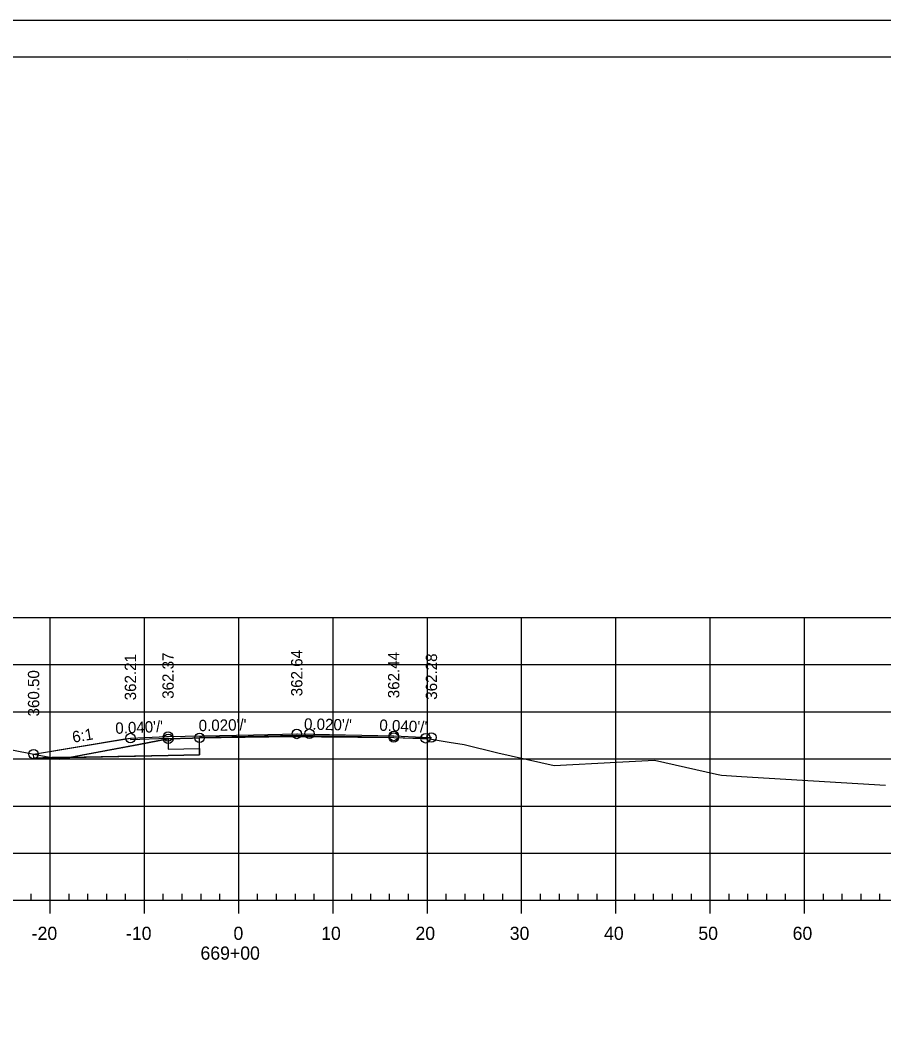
# Model space of a CAD drawing. Extents: x 1359801 to 1362404, y 372415 to 374228.
# Drawn here: x 1359948.2 to 1360039.8, y 373694.6 to 373801.3 of the extents above; entities that cross this region are included whole.
import ezdxf

# ---------------------------------------------------------------- set-up
doc = ezdxf.new("R2010")
doc.units = 0
for name, color, linetype in [('S_DRG_PT_SYM', 7, 'Continuous'), ('S_ELECTRIC_UTILITIES_ANNOT', 7, 'Continuous'), ('S_IRON_PIN', 7, 'Continuous'), ('S_MAILBOX', 7, 'Continuous'), ('S_PRIMARY_CTL', 7, 'Continuous'), ('S_SANITARY_SEWER', 7, 'Continuous'), ('S_SHOULDER', 7, 'Continuous'), ('S_UNDERGROUND_CABLE', 7, 'Continuous'), ('S_UTL_PT_SYM', 7, 'Continuous'), ('S_WATER_UTILITIES', 7, 'Continuous')]:
    doc.layers.add(name, color=color, linetype=linetype)

msp = doc.modelspace()

# ---------------------------------------------------------------- linework, layer by layer
at = {"layer": 'S_DRG_PT_SYM'}
msp.add_lwpolyline([(1359936.81, 373725.9), (1359952.38, 373722.9), (1359960.74, 373724.47), (1359963.88, 373725.06), (1359966.43, 373725.14), (1359967.2, 373725.16), (1359969.5, 373725.19), (1359977.07, 373725.3), (1359980.14, 373725.27), (1359987.78, 373725.21), (1359990.13, 373725.15), (1359991.16, 373725.12), (1359993.65, 373724.7), (1359995.24, 373724.46), (1359998.82, 373723.57), (1360004.81, 373722.25), (1360011.41, 373722.59), (1360015.44, 373722.79), (1360022.02, 373721.32), (1360022.56, 373721.21), (1360024.66, 373721.07), (1360039.94, 373720.16)], dxfattribs=at)
at = {"layer": 'S_ELECTRIC_UTILITIES_ANNOT'}
for p, q in [((1359987.78, 373725.21), (1359977.5, 373725.41)), ((1359953.44, 373723.1), (1359951.54, 373723.07)), ((1359951.54, 373723.07), (1359951.54, 373723.07)), ((1359953.44, 373723.1), (1359963.85, 373723.31))]:
    msp.add_line(p, q, dxfattribs=at)
for points in [[(1359967.2, 373725.16), (1359966.43, 373725.14), (1359963.88, 373725.06), (1359960.74, 373724.47), (1359953.44, 373723.1)], [(1359963.85, 373723.31), (1359967.2, 373723.38), (1359967.2, 373725.16)], [(1359977.5, 373725.41), (1359967.2, 373725.21), (1359967.2, 373725.16)], [(1359967.2, 373725.16), (1359969.5, 373725.19), (1359977.07, 373725.3), (1359980.14, 373725.27), (1359987.78, 373725.21)], [(1359951.54, 373723.07), (1359952.38, 373722.9), (1359953.44, 373723.1)]]:
    msp.add_lwpolyline(points, dxfattribs=at)
msp.add_lwpolyline([(1359949.6, 373723.03), (1359949.59, 373723.44), (1359951.54, 373723.07)], close=True, dxfattribs=at)
at = {"layer": 'S_MAILBOX'}
for p, q in [((1359826.35, 373737.94), (1360116.35, 373737.94)), ((1359951.35, 373707.94), (1359951.35, 373737.94)), ((1359961.35, 373707.94), (1359961.35, 373737.94)), ((1359971.35, 373707.94), (1359971.35, 373737.94)), ((1359981.35, 373707.94), (1359981.35, 373737.94)), ((1359991.35, 373707.94), (1359991.35, 373737.94)), ((1360001.35, 373707.94), (1360001.35, 373737.94)), ((1360011.35, 373707.94), (1360011.35, 373737.94)), ((1360021.35, 373707.94), (1360021.35, 373737.94)), ((1360031.35, 373707.94), (1360031.35, 373737.94)), ((1359826.35, 373732.94), (1360116.35, 373732.94)), ((1359826.35, 373727.94), (1360116.35, 373727.94)), ((1359826.35, 373722.94), (1360116.35, 373722.94)), ((1359826.35, 373717.94), (1360116.35, 373717.94)), ((1359826.35, 373712.94), (1360116.35, 373712.94)), ((1359826.35, 373707.94), (1360116.35, 373707.94))]:
    msp.add_line(p, q, dxfattribs=at)
at = {"layer": 'S_SANITARY_SEWER'}
msp.add_lwpolyline([(1359949.59, 373723.44), (1359959.25, 373725.05), (1359959.86, 373725.15), (1359963.7, 373725.3), (1359963.85, 373725.31), (1359972.91, 373725.49), (1359977.5, 373725.58), (1359977.57, 373725.58), (1359977.57, 373725.58), (1359977.57, 373725.58), (1359987.78, 373725.37), (1359990.88, 373725.25), (1359991.78, 373725.21)], dxfattribs=at)
at = {"layer": 'S_SHOULDER'}
msp.add_line((1359800.95, 373801.29), (1360134.28, 373801.29), dxfattribs=at)
for points in [[(1359800.94, 373801.29), (1360134.28, 373801.29), (1360134.28, 373587.95), (1359800.94, 373587.95)], [(1360047.27, 373797.4), (1360047.27, 373787.52), (1360083, 373787.52), (1360083, 373784.6), (1360106.2, 373784.6), (1360106.2, 373760.26), (1360129.53, 373760.26), (1360129.53, 373591.94), (1359813.35, 373591.94), (1359813.35, 373797.4)]]:
    msp.add_lwpolyline(points, close=True, dxfattribs=at)
for points in [[(1359949.59, 373723.44), (1359959.86, 373725.15), (1359959.87, 373724.98), (1359963.86, 373725.14)], [(1359963.86, 373725.14), (1359963.88, 373723.98), (1359967.2, 373724.04)], [(1359967.2, 373724.04), (1359967.2, 373723.38), (1359963.85, 373723.31), (1359949.6, 373723.03), (1359949.59, 373723.44)]]:
    msp.add_lwpolyline(points, dxfattribs=at)
for centre in [(1359977.5, 373725.58), (1359978.85, 373725.61), (1359959.86, 373725.15), (1359963.85, 373725.31), (1359963.88, 373725.06), (1359967.2, 373725.16), (1359987.78, 373725.37), (1359987.78, 373725.21), (1359991.16, 373725.12), (1359991.78, 373725.21), (1359949.59, 373723.44)]:
    msp.add_circle(centre, 0.5, dxfattribs=at)
at = {"layer": 'S_UNDERGROUND_CABLE'}
msp.add_lwpolyline([(1359949.6, 373723.03), (1359963.85, 373723.31), (1359967.2, 373723.38), (1359967.2, 373725.21), (1359977.5, 373725.41), (1359987.78, 373725.21), (1359991.78, 373725.05)], dxfattribs=at)
at = {"layer": 'S_UTL_PT_SYM'}
for p, q in [((1359813.35, 373797.4), (1360129.53, 373797.4)), ((1359965.87, 373797.14), (1359965.87, 373797.14)), ((1359965.87, 373797.14), (1359965.87, 373797.14))]:
    msp.add_line(p, q, dxfattribs=at)
at = {"layer": 'S_WATER_UTILITIES'}
for p, q in [((1359826.35, 373707.94), (1360116.35, 373707.94)), ((1359949.35, 373707.94), (1359949.35, 373708.64)), ((1359951.35, 373706.54), (1359951.35, 373707.94)), ((1359953.35, 373707.94), (1359953.35, 373708.64)), ((1359955.35, 373707.94), (1359955.35, 373708.64)), ((1359957.35, 373707.94), (1359957.35, 373708.64)), ((1359959.35, 373707.94), (1359959.35, 373708.64)), ((1359961.35, 373706.54), (1359961.35, 373707.94)), ((1359963.35, 373707.94), (1359963.35, 373708.64)), ((1359965.35, 373707.94), (1359965.35, 373708.64)), ((1359967.35, 373707.94), (1359967.35, 373708.64)), ((1359969.35, 373707.94), (1359969.35, 373708.64)), ((1359971.35, 373706.54), (1359971.35, 373707.94)), ((1359973.35, 373707.94), (1359973.35, 373708.64)), ((1359975.35, 373707.94), (1359975.35, 373708.64)), ((1359977.35, 373707.94), (1359977.35, 373708.64)), ((1359979.35, 373707.94), (1359979.35, 373708.64)), ((1359981.35, 373706.54), (1359981.35, 373707.94)), ((1359983.35, 373707.94), (1359983.35, 373708.64)), ((1359985.35, 373707.94), (1359985.35, 373708.64)), ((1359987.35, 373707.94), (1359987.35, 373708.64)), ((1359989.35, 373707.94), (1359989.35, 373708.64)), ((1359991.35, 373706.54), (1359991.35, 373707.94)), ((1359993.35, 373707.94), (1359993.35, 373708.64)), ((1359995.35, 373707.94), (1359995.35, 373708.64)), ((1359997.35, 373707.94), (1359997.35, 373708.64)), ((1359999.35, 373707.94), (1359999.35, 373708.64)), ((1360001.35, 373706.54), (1360001.35, 373707.94)), ((1360003.35, 373707.94), (1360003.35, 373708.64)), ((1360005.35, 373707.94), (1360005.35, 373708.64)), ((1360007.35, 373707.94), (1360007.35, 373708.64)), ((1360009.35, 373707.94), (1360009.35, 373708.64)), ((1360011.35, 373706.54), (1360011.35, 373707.94)), ((1360013.35, 373707.94), (1360013.35, 373708.64)), ((1360015.35, 373707.94), (1360015.35, 373708.64)), ((1360017.35, 373707.94), (1360017.35, 373708.64)), ((1360019.35, 373707.94), (1360019.35, 373708.64)), ((1360021.35, 373706.54), (1360021.35, 373707.94)), ((1360023.35, 373707.94), (1360023.35, 373708.64)), ((1360025.35, 373707.94), (1360025.35, 373708.64)), ((1360027.35, 373707.94), (1360027.35, 373708.64)), ((1360029.35, 373707.94), (1360029.35, 373708.64)), ((1360031.35, 373706.54), (1360031.35, 373707.94)), ((1360033.35, 373707.94), (1360033.35, 373708.64)), ((1360035.35, 373707.94), (1360035.35, 373708.64)), ((1360037.35, 373707.94), (1360037.35, 373708.64)), ((1360039.35, 373707.94), (1360039.35, 373708.64))]:
    msp.add_line(p, q, dxfattribs=at)

# ---------------------------------------------------------------- texts
at = {"layer": 'S_IRON_PIN'}
for s, rotation, p in [('362.64', 90, (1359978.1, 373729.58)), ('362.21', 90, (1359960.46, 373729.15)), ('362.37', 90, (1359964.45, 373729.31)), ('362.44', 90, (1359988.38, 373729.37)), ('362.28', 90, (1359992.38, 373729.21)), ('360.50', 90, (1359950.19, 373727.44)), ("0.040'/'", 2.2809, (1359958.28, 373725.59)), ("0.020'/'", 1.1353, (1359967.11, 373725.87)), ("0.020'/'", 358.6978, (1359978.26, 373726.05)), ("0.040'/'", 357.7013, (1359986.24, 373725.93)), ('6:1', 9.4571, (1359953.79, 373724.65))]:
    msp.add_text(s, height=1.2, rotation=rotation, dxfattribs=at).set_placement(p)
at = {"layer": 'S_PRIMARY_CTL'}
for s, p in [('-20', (1359949.39, 373703.74)), ('-10', (1359959.39, 373703.74)), ('0', (1359970.79, 373703.74)), ('10', (1359980.09, 373703.74)), ('20', (1359990.09, 373703.74)), ('30', (1360000.09, 373703.74)), ('40', (1360010.09, 373703.74)), ('50', (1360020.09, 373703.74)), ('60', (1360030.09, 373703.74)), ('669+00', (1359967.29, 373701.64))]:
    msp.add_text(s, height=1.4, dxfattribs=at).set_placement(p)

doc.saveas('drawing.dxf')
